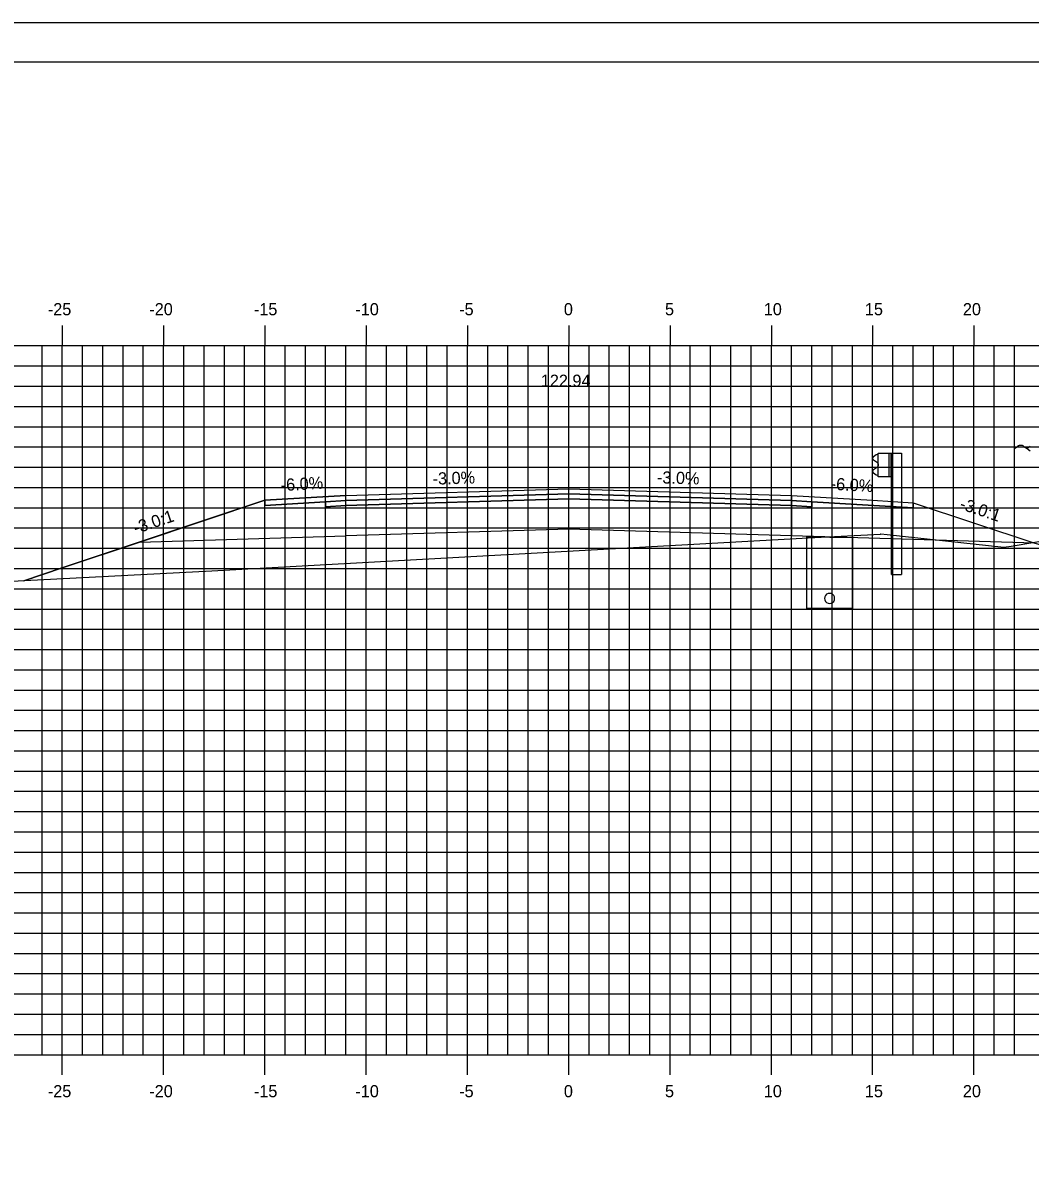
# Model space of a CAD drawing. Extents: x 850598 to 870284, y 366541 to 366651.
# Drawn here: x 855280.8 to 855330.6, y 366595.1 to 366651.2 of the extents above; entities that cross this region are included whole.
import ezdxf

# ---------------------------------------------------------------- set-up
doc = ezdxf.new("R2010")
doc.units = 0
for name, color, linetype in [('ANNOTATION', 7, 'Continuous'), ('BORDER', 7, 'Continuous'), ('D_Drainage_Underdrain', 7, 'Continuous'), ('D_Drainage_Underdrain_06in', 7, 'Continuous'), ('D_Guardrail_Beam_Rt', 7, 'Continuous'), ('D_Roadway_Centerline', 7, 'Continuous'), ('D_Roadway_Centerline_Text', 7, 'Continuous'), ('D_Roadway_Edge_Shoulder', 7, 'Continuous'), ('D_Roadway_Edge_TW', 7, 'Continuous'), ('D_Roadway_Pavement', 7, 'Continuous'), ('D_Roadway_SlopeLines', 7, 'Continuous'), ('D_Roadway_SubGrade', 7, 'Continuous'), ('D_Utilities_Pole_Joint', 7, 'Continuous'), ('H_V ANNOTATION', 7, 'Continuous'), ('MAJOR', 7, 'Continuous'), ('MINOR', 7, 'Continuous'), ('PLOT BOUNDARY', 7, 'Continuous'), ('S_Roadway_Centerline', 7, 'Continuous')]:
    doc.layers.add(name, color=color, linetype=linetype)

msp = doc.modelspace()

# ---------------------------------------------------------------- linework, layer by layer
at = {"layer": 'BORDER'}
msp.add_line((855422.785, 366649.225), (855262.785, 366649.225), dxfattribs=at)
at = {"layer": 'D_Drainage_Underdrain'}
msp.add_lwpolyline([(855321.784, 366625.75), (855321.784, 366622.249), (855319.534, 366622.249), (855319.534, 366625.795)], close=True, dxfattribs=at)
at = {"layer": 'D_Drainage_Underdrain_06in'}
msp.add_lwpolyline([(855320.659, 366622.999), (855320.582, 366622.987), (855320.512, 366622.952), (855320.457, 366622.896), (855320.422, 366622.827), (855320.409, 366622.749), (855320.422, 366622.672), (855320.457, 366622.602), (855320.512, 366622.547), (855320.582, 366622.512), (855320.659, 366622.499), (855320.737, 366622.512), (855320.806, 366622.547), (855320.862, 366622.602), (855320.897, 366622.672), (855320.909, 366622.749), (855320.897, 366622.827), (855320.862, 366622.896), (855320.806, 366622.952), (855320.737, 366622.987)], close=True, dxfattribs=at)
at = {"layer": 'D_Guardrail_Beam_Rt'}
for p, q in [((855322.965, 366629.831), (855322.822, 366629.731)), ((855322.822, 366629.588), (855323.017, 366629.452)), ((855323.055, 366629.851), (855322.982, 366629.838)), ((855323.055, 366629.925), (855323.743, 366629.925)), ((855323.055, 366628.758), (855323.055, 366629.925)), ((855323.576, 366629.925), (855323.576, 366628.758)), ((855323.68, 366629.925), (855323.68, 366628.758)), ((855323.743, 366629.925), (855324.214, 366629.925)), ((855323.743, 366629.925), (855323.743, 366628.758)), ((855324.214, 366629.925), (855324.214, 366623.925)), ((855323.017, 366629.232), (855322.822, 366629.096)), ((855322.822, 366628.953), (855322.965, 366628.853)), ((855323.051, 366629.387), (855323.051, 366629.296)), ((855322.982, 366628.846), (855323.055, 366628.833)), ((855323.743, 366628.758), (855323.055, 366628.758)), ((855323.722, 366623.925), (855323.722, 366628.758)), ((855323.722, 366623.925), (855324.214, 366623.925))]:
    msp.add_line(p, q, dxfattribs=at)
for centre, major_axis, start_param, end_param in [((855322.872, 366629.659), (-0.0877, 0), 5.323254, 7.243116), ((855322.989, 366629.797), (-0.0417, 0), 4.886922, 5.323254), ((855322.972, 366629.387), (0.0789, 0), 0, 0.959931), ((855322.872, 366629.024), (-0.0877, 0), 5.323254, 7.243116), ((855322.972, 366629.296), (0.0789, 0), 5.323254, 6.283185), ((855322.989, 366628.887), (-0.0417, 0), 0.959931, 1.396263)]:
    msp.add_ellipse(centre, major_axis=major_axis, ratio=0.995501, start_param=start_param, end_param=end_param, dxfattribs=at)
at = {"layer": 'D_Roadway_Centerline'}
msp.add_lwpolyline([(855280.878, 366623.623), (855282.784, 366624.259), (855286.587, 366625.526), (855292.784, 366627.592), (855296.784, 366627.832), (855307.784, 366628.162), (855318.784, 366627.832), (855322.784, 366627.592), (855324.784, 366627.472), (855330.784, 366625.472), (855377.517, 366613.225), (855390.551, 366609.81), (855400.413, 366607.225), (855404.413, 366607.225)], dxfattribs=at)
at = {"layer": 'D_Roadway_Edge_Shoulder'}
for points in [[(855296.784, 366627.832), (855292.784, 366627.592), (855292.784, 366627.342), (855295.784, 366627.522), (855296.784, 366627.582)], [(855318.784, 366627.832), (855322.784, 366627.592), (855322.784, 366627.592), (855324.784, 366627.472), (855324.784, 366627.222), (855319.784, 366627.522), (855318.784, 366627.582)]]:
    msp.add_lwpolyline(points, close=True, dxfattribs=at)
at = {"layer": 'D_Roadway_Edge_TW'}
msp.add_lwpolyline([(855296.784, 366627.582), (855296.784, 366627.832), (855307.784, 366628.162), (855318.784, 366627.832), (855318.784, 366627.582), (855307.784, 366627.912)], close=True, dxfattribs=at)
at = {"layer": 'D_Roadway_Pavement'}
for points in [[(855296.784, 366627.332), (855296.784, 366627.582), (855307.784, 366627.912), (855318.784, 366627.582), (855318.784, 366627.332), (855307.784, 366627.662)], [(855296.784, 366627.582), (855295.784, 366627.522), (855295.784, 366627.272), (855296.784, 366627.332)], [(855318.784, 366627.582), (855319.784, 366627.522), (855319.784, 366627.272), (855318.784, 366627.332)]]:
    msp.add_lwpolyline(points, close=True, dxfattribs=at)
at = {"layer": 'D_Roadway_SlopeLines'}
for points in [[(855296.784, 366627.832), (855292.784, 366627.592), (855282.784, 366624.259)], [(855282.784, 366624.259), (855280.878, 366623.623)]]:
    msp.add_lwpolyline(points, dxfattribs=at)
at = {"layer": 'D_Roadway_SubGrade'}
for points in [[(855296.784, 366627.332), (855295.784, 366627.272), (855295.784, 366627.522), (855292.784, 366627.342), (855292.784, 366627.592), (855286.587, 366625.526), (855296.784, 366625.832)], [(855296.784, 366625.832), (855296.784, 366627.332), (855307.784, 366627.662), (855318.784, 366627.332), (855318.784, 366625.832), (855307.784, 366626.162)], [(855318.784, 366627.332), (855319.784, 366627.272), (855319.784, 366627.522), (855324.784, 366627.222), (855324.784, 366627.472), (855330.784, 366625.472), (855318.784, 366625.832)]]:
    msp.add_lwpolyline(points, close=True, dxfattribs=at)
at = {"layer": 'D_Utilities_Pole_Joint'}
for p, q in [((855329.784, 366630.142), (855329.941, 366630.253)), ((855329.784, 366625.385), (855329.784, 366630.142)), ((855330.253, 366630.253), (855330.409, 366630.142)), ((855330.565, 366630.253), (855330.409, 366630.142)), ((855330.409, 366630.142), (855330.565, 366630.032))]:
    msp.add_line(p, q, dxfattribs=at)
for start, end in [(90, 125.2644), (54.7356, 90)]:
    msp.add_arc((855330.097, 366630.032), 0.271, start, end, dxfattribs=at)
at = {"layer": 'MAJOR'}
for p, q in [((855282.784, 366636.227), (855282.784, 366635.225)), ((855282.784, 366636.227), (855282.784, 366635.225)), ((855287.784, 366636.227), (855287.784, 366635.225)), ((855287.784, 366636.227), (855287.784, 366635.225)), ((855292.784, 366636.227), (855292.784, 366635.225)), ((855292.784, 366636.227), (855292.784, 366635.225)), ((855297.784, 366636.227), (855297.784, 366635.225)), ((855297.784, 366636.227), (855297.784, 366635.225)), ((855302.784, 366636.227), (855302.784, 366635.225)), ((855302.784, 366636.227), (855302.784, 366635.225)), ((855307.784, 366636.227), (855307.784, 366635.225)), ((855307.784, 366636.227), (855307.784, 366635.225)), ((855312.784, 366636.227), (855312.784, 366635.225)), ((855312.784, 366636.227), (855312.784, 366635.225)), ((855317.784, 366636.227), (855317.784, 366635.225)), ((855317.784, 366636.227), (855317.784, 366635.225)), ((855322.784, 366636.227), (855322.784, 366635.225)), ((855322.784, 366636.227), (855322.784, 366635.225)), ((855327.784, 366636.227), (855327.784, 366635.225)), ((855327.784, 366636.227), (855327.784, 366635.225)), ((855267.784, 366635.225), (855407.784, 366635.225)), ((855267.784, 366635.225), (855407.784, 366635.225)), ((855267.784, 366635.225), (855407.784, 366635.225)), ((855267.784, 366635.225), (855407.784, 366635.225)), ((855282.784, 366600.225), (855282.784, 366635.225)), ((855282.784, 366600.225), (855282.784, 366635.225)), ((855287.784, 366600.225), (855287.784, 366635.225)), ((855287.784, 366600.225), (855287.784, 366635.225)), ((855292.784, 366600.225), (855292.784, 366635.225)), ((855292.784, 366600.225), (855292.784, 366635.225)), ((855297.784, 366600.225), (855297.784, 366635.225)), ((855297.784, 366600.225), (855297.784, 366635.225)), ((855302.784, 366600.225), (855302.784, 366635.225)), ((855302.784, 366600.225), (855302.784, 366635.225)), ((855307.784, 366600.225), (855307.784, 366635.225)), ((855307.784, 366600.225), (855307.784, 366635.225)), ((855312.784, 366600.225), (855312.784, 366635.225)), ((855312.784, 366600.225), (855312.784, 366635.225)), ((855317.784, 366600.225), (855317.784, 366635.225)), ((855317.784, 366600.225), (855317.784, 366635.225)), ((855322.784, 366600.225), (855322.784, 366635.225)), ((855322.784, 366600.225), (855322.784, 366635.225)), ((855327.784, 366600.225), (855327.784, 366635.225)), ((855327.784, 366600.225), (855327.784, 366635.225)), ((855267.784, 366630.225), (855407.784, 366630.225)), ((855267.784, 366630.225), (855407.784, 366630.225)), ((855267.784, 366625.225), (855407.784, 366625.225)), ((855267.784, 366625.225), (855407.784, 366625.225)), ((855267.784, 366620.225), (855407.784, 366620.225)), ((855267.784, 366620.225), (855407.784, 366620.225)), ((855267.784, 366615.225), (855407.784, 366615.225)), ((855267.784, 366615.225), (855407.784, 366615.225)), ((855267.784, 366610.225), (855407.784, 366610.225)), ((855267.784, 366610.225), (855407.784, 366610.225)), ((855267.784, 366605.225), (855407.784, 366605.225)), ((855267.784, 366605.225), (855407.784, 366605.225)), ((855267.784, 366600.225), (855407.784, 366600.225)), ((855267.784, 366600.225), (855407.784, 366600.225)), ((855267.784, 366600.225), (855407.784, 366600.225)), ((855267.784, 366600.225), (855407.784, 366600.225)), ((855282.784, 366599.223), (855282.784, 366600.225)), ((855282.784, 366599.223), (855282.784, 366600.225)), ((855287.784, 366599.223), (855287.784, 366600.225)), ((855287.784, 366599.223), (855287.784, 366600.225)), ((855292.784, 366599.223), (855292.784, 366600.225)), ((855292.784, 366599.223), (855292.784, 366600.225)), ((855297.784, 366599.223), (855297.784, 366600.225)), ((855297.784, 366599.223), (855297.784, 366600.225)), ((855302.784, 366599.223), (855302.784, 366600.225)), ((855302.784, 366599.223), (855302.784, 366600.225)), ((855307.784, 366599.223), (855307.784, 366600.225)), ((855307.784, 366599.223), (855307.784, 366600.225)), ((855312.784, 366599.223), (855312.784, 366600.225)), ((855312.784, 366599.223), (855312.784, 366600.225)), ((855317.784, 366599.223), (855317.784, 366600.225)), ((855317.784, 366599.223), (855317.784, 366600.225)), ((855322.784, 366599.223), (855322.784, 366600.225)), ((855322.784, 366599.223), (855322.784, 366600.225)), ((855327.784, 366599.223), (855327.784, 366600.225)), ((855327.784, 366599.223), (855327.784, 366600.225))]:
    msp.add_line(p, q, dxfattribs=at)
at = {"layer": 'MINOR'}
for p, q in [((855281.784, 366600.225), (855281.784, 366635.225)), ((855281.784, 366600.225), (855281.784, 366635.225)), ((855283.784, 366600.225), (855283.784, 366635.225)), ((855283.784, 366600.225), (855283.784, 366635.225)), ((855284.784, 366600.225), (855284.784, 366635.225)), ((855284.784, 366600.225), (855284.784, 366635.225)), ((855285.784, 366600.225), (855285.784, 366635.225)), ((855285.784, 366600.225), (855285.784, 366635.225)), ((855286.784, 366600.225), (855286.784, 366635.225)), ((855286.784, 366600.225), (855286.784, 366635.225)), ((855288.784, 366600.225), (855288.784, 366635.225)), ((855288.784, 366600.225), (855288.784, 366635.225)), ((855289.784, 366600.225), (855289.784, 366635.225)), ((855289.784, 366600.225), (855289.784, 366635.225)), ((855290.784, 366600.225), (855290.784, 366635.225)), ((855290.784, 366600.225), (855290.784, 366635.225)), ((855291.784, 366600.225), (855291.784, 366635.225)), ((855291.784, 366600.225), (855291.784, 366635.225)), ((855293.784, 366600.225), (855293.784, 366635.225)), ((855293.784, 366600.225), (855293.784, 366635.225)), ((855294.784, 366600.225), (855294.784, 366635.225)), ((855294.784, 366600.225), (855294.784, 366635.225)), ((855295.784, 366600.225), (855295.784, 366635.225)), ((855295.784, 366600.225), (855295.784, 366635.225)), ((855296.784, 366600.225), (855296.784, 366635.225)), ((855296.784, 366600.225), (855296.784, 366635.225)), ((855298.784, 366600.225), (855298.784, 366635.225)), ((855298.784, 366600.225), (855298.784, 366635.225)), ((855299.784, 366600.225), (855299.784, 366635.225)), ((855299.784, 366600.225), (855299.784, 366635.225)), ((855300.784, 366600.225), (855300.784, 366635.225)), ((855300.784, 366600.225), (855300.784, 366635.225)), ((855301.784, 366600.225), (855301.784, 366635.225)), ((855301.784, 366600.225), (855301.784, 366635.225)), ((855303.784, 366600.225), (855303.784, 366635.225)), ((855303.784, 366600.225), (855303.784, 366635.225)), ((855304.784, 366600.225), (855304.784, 366635.225)), ((855304.784, 366600.225), (855304.784, 366635.225)), ((855305.784, 366600.225), (855305.784, 366635.225)), ((855305.784, 366600.225), (855305.784, 366635.225)), ((855306.784, 366600.225), (855306.784, 366635.225)), ((855306.784, 366600.225), (855306.784, 366635.225)), ((855308.784, 366600.225), (855308.784, 366635.225)), ((855308.784, 366600.225), (855308.784, 366635.225)), ((855309.784, 366600.225), (855309.784, 366635.225)), ((855309.784, 366600.225), (855309.784, 366635.225)), ((855310.784, 366600.225), (855310.784, 366635.225)), ((855310.784, 366600.225), (855310.784, 366635.225)), ((855311.784, 366600.225), (855311.784, 366635.225)), ((855311.784, 366600.225), (855311.784, 366635.225)), ((855313.784, 366600.225), (855313.784, 366635.225)), ((855313.784, 366600.225), (855313.784, 366635.225)), ((855314.784, 366600.225), (855314.784, 366635.225)), ((855314.784, 366600.225), (855314.784, 366635.225)), ((855315.784, 366600.225), (855315.784, 366635.225)), ((855315.784, 366600.225), (855315.784, 366635.225)), ((855316.784, 366600.225), (855316.784, 366635.225)), ((855316.784, 366600.225), (855316.784, 366635.225)), ((855318.784, 366600.225), (855318.784, 366635.225)), ((855318.784, 366600.225), (855318.784, 366635.225)), ((855319.784, 366600.225), (855319.784, 366635.225)), ((855319.784, 366600.225), (855319.784, 366635.225)), ((855320.784, 366600.225), (855320.784, 366635.225)), ((855320.784, 366600.225), (855320.784, 366635.225)), ((855321.784, 366600.225), (855321.784, 366635.225)), ((855321.784, 366600.225), (855321.784, 366635.225)), ((855323.784, 366600.225), (855323.784, 366635.225)), ((855323.784, 366600.225), (855323.784, 366635.225)), ((855324.784, 366600.225), (855324.784, 366635.225)), ((855324.784, 366600.225), (855324.784, 366635.225)), ((855325.784, 366600.225), (855325.784, 366635.225)), ((855325.784, 366600.225), (855325.784, 366635.225)), ((855326.784, 366600.225), (855326.784, 366635.225)), ((855326.784, 366600.225), (855326.784, 366635.225)), ((855328.784, 366600.225), (855328.784, 366635.225)), ((855328.784, 366600.225), (855328.784, 366635.225)), ((855329.784, 366600.225), (855329.784, 366635.225)), ((855329.784, 366600.225), (855329.784, 366635.225)), ((855267.784, 366634.225), (855407.784, 366634.225)), ((855267.784, 366634.225), (855407.784, 366634.225)), ((855267.784, 366633.225), (855407.784, 366633.225)), ((855267.784, 366633.225), (855407.784, 366633.225)), ((855267.784, 366632.225), (855407.784, 366632.225)), ((855267.784, 366632.225), (855407.784, 366632.225)), ((855267.784, 366631.225), (855407.784, 366631.225)), ((855267.784, 366631.225), (855407.784, 366631.225)), ((855267.784, 366629.225), (855407.784, 366629.225)), ((855267.784, 366629.225), (855407.784, 366629.225)), ((855267.784, 366628.225), (855407.784, 366628.225)), ((855267.784, 366628.225), (855407.784, 366628.225)), ((855267.784, 366627.225), (855407.784, 366627.225)), ((855267.784, 366627.225), (855407.784, 366627.225)), ((855267.784, 366626.225), (855407.784, 366626.225)), ((855267.784, 366626.225), (855407.784, 366626.225)), ((855267.784, 366624.225), (855407.784, 366624.225)), ((855267.784, 366624.225), (855407.784, 366624.225)), ((855267.784, 366623.225), (855407.784, 366623.225)), ((855267.784, 366623.225), (855407.784, 366623.225)), ((855267.784, 366622.225), (855407.784, 366622.225)), ((855267.784, 366622.225), (855407.784, 366622.225)), ((855267.784, 366621.225), (855407.784, 366621.225)), ((855267.784, 366621.225), (855407.784, 366621.225)), ((855267.784, 366619.225), (855407.784, 366619.225)), ((855267.784, 366619.225), (855407.784, 366619.225)), ((855267.784, 366618.225), (855407.784, 366618.225)), ((855267.784, 366618.225), (855407.784, 366618.225)), ((855267.784, 366617.225), (855407.784, 366617.225)), ((855267.784, 366617.225), (855407.784, 366617.225)), ((855267.784, 366616.225), (855407.784, 366616.225)), ((855267.784, 366616.225), (855407.784, 366616.225)), ((855267.784, 366614.225), (855407.784, 366614.225)), ((855267.784, 366614.225), (855407.784, 366614.225)), ((855267.784, 366613.225), (855407.784, 366613.225)), ((855267.784, 366613.225), (855407.784, 366613.225)), ((855267.784, 366612.225), (855407.784, 366612.225)), ((855267.784, 366612.225), (855407.784, 366612.225)), ((855267.784, 366611.225), (855407.784, 366611.225)), ((855267.784, 366611.225), (855407.784, 366611.225)), ((855267.784, 366609.225), (855407.784, 366609.225)), ((855267.784, 366609.225), (855407.784, 366609.225)), ((855267.784, 366608.225), (855407.784, 366608.225)), ((855267.784, 366608.225), (855407.784, 366608.225)), ((855267.784, 366607.225), (855407.784, 366607.225)), ((855267.784, 366607.225), (855407.784, 366607.225)), ((855267.784, 366606.225), (855407.784, 366606.225)), ((855267.784, 366606.225), (855407.784, 366606.225)), ((855267.784, 366604.225), (855407.784, 366604.225)), ((855267.784, 366604.225), (855407.784, 366604.225)), ((855267.784, 366603.225), (855407.784, 366603.225)), ((855267.784, 366603.225), (855407.784, 366603.225)), ((855267.784, 366602.225), (855407.784, 366602.225)), ((855267.784, 366602.225), (855407.784, 366602.225)), ((855267.784, 366601.225), (855407.784, 366601.225)), ((855267.784, 366601.225), (855407.784, 366601.225))]:
    msp.add_line(p, q, dxfattribs=at)
at = {"layer": 'PLOT BOUNDARY'}
msp.add_lwpolyline([(855254.691, 366541.166), (855424.691, 366541.166), (855424.691, 366651.166), (855254.691, 366651.166)], close=True, dxfattribs=at)
at = {"layer": 'S_Roadway_Centerline'}
msp.add_lwpolyline([(855267.784, 366622.994), (855273.245, 366623.23), (855290.17, 366624.102), (855319.61, 366625.731), (855323.174, 366625.923), (855323.19, 366625.928), (855323.503, 366625.906), (855329.259, 366625.283), (855329.625, 366625.334), (855334.576, 366626.167), (855338.301, 366626.78), (855338.437, 366626.81), (855353.074, 366627.397), (855353.325, 366627.407), (855353.743, 366627.392), (855369.087, 366626.531), (855369.346, 366626.471), (855372.92, 366625.288), (855385.59, 366616.285), (855386.151, 366615.915), (855392.813, 366611.219), (855393.897, 366610.848), (855407.784, 366606.064)], dxfattribs=at)

# ---------------------------------------------------------------- texts
at = {"layer": 'ANNOTATION'}
for s, rotation, p in [('-3.0%', 1.7184, (855301.072, 366628.361)), ('-3.0%', 358.2816, (855312.132, 366628.432)), ('-6.0%', 3.4336, (855293.582, 366628.041)), ('-6.0%', 356.5664, (855320.701, 366628.119)), ('-3.0:1', 341.5651, (855327.038, 366627.175)), ('-3.0:1', 18.4348, (855286.406, 366625.92))]:
    msp.add_text(s, height=0.6, rotation=rotation, dxfattribs=at).set_placement(p)
at = {"layer": 'D_Roadway_Centerline'}
for s, p in [('C', (855307.779, 366628.162)), ('C', (855307.779, 366628.162)), ('L', (855307.784, 366628.155)), ('L', (855307.784, 366628.155))]:
    msp.add_text(s, height=0.0146, dxfattribs=at).set_placement(p)
at = {"layer": 'D_Roadway_Centerline_Text'}
msp.add_text('122.94', height=0.6, dxfattribs=at).set_placement((855306.404, 366633.194))
at = {"layer": 'H_V ANNOTATION'}
for s, p in [('-25', (855282.07, 366636.725)), ('-20', (855287.078, 366636.725)), ('-15', (855292.241, 366636.725)), ('-10', (855297.249, 366636.725)), ('-5', (855302.375, 366636.725)), ('0', (855307.543, 366636.725)), ('5', (855312.535, 366636.725)), ('10', (855317.41, 366636.725)), ('15', (855322.402, 366636.725)), ('20', (855327.238, 366636.725)), ('-25', (855282.07, 366598.125)), ('-20', (855287.078, 366598.125)), ('-15', (855292.241, 366598.125)), ('-10', (855297.249, 366598.125)), ('-5', (855302.375, 366598.125)), ('0', (855307.543, 366598.125)), ('5', (855312.535, 366598.125)), ('10', (855317.41, 366598.125)), ('15', (855322.402, 366598.125)), ('20', (855327.238, 366598.125))]:
    msp.add_text(s, height=0.6, dxfattribs=at).set_placement(p)

doc.saveas('drawing.dxf')
